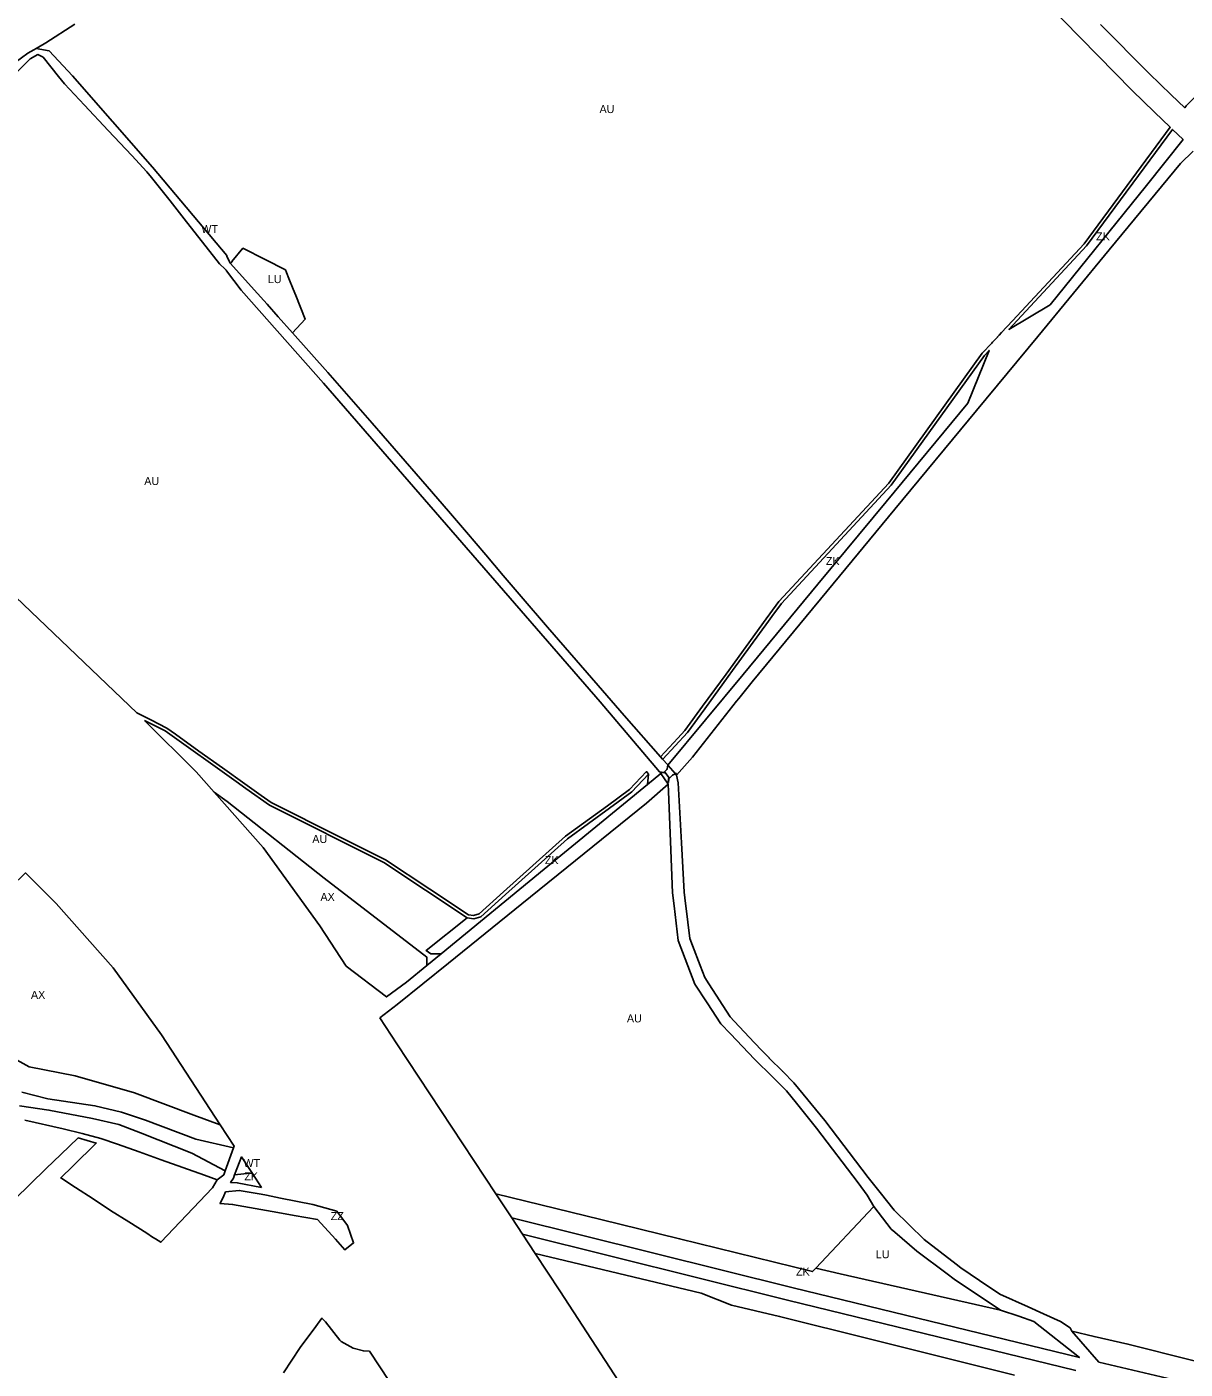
# Model space of a CAD drawing. Extents: x -545779 to -541342, y -1153413 to -1149956.
# Drawn here: x -543834 to -543110, y -1151300 to -1150461 of the extents above; entities that cross this region are included whole.
import ezdxf

# ---------------------------------------------------------------- set-up
doc = ezdxf.new("R2010")
doc.units = 0
for name, color, linetype in [('90640013', 7, 'Continuous'), ('90670013', 7, 'Continuous'), ('90710013', 7, 'Continuous'), ('90750013', 7, 'Continuous'), ('90760013', 7, 'Continuous'), ('90770013', 7, 'Continuous'), ('90910012', 7, 'Continuous')]:
    doc.layers.add(name, color=color, linetype=linetype)

msp = doc.modelspace()

# ---------------------------------------------------------------- linework, layer by layer
at = {"layer": '90640013'}
for points in [[(-543856.96, -1150495.34), (-543832.89, -1150477.96), (-543829.16, -1150475.78), (-543827.7, -1150474.93), (-543819.62, -1150476.53), (-543805.09, -1150492.17), (-543755.13, -1150549.13), (-543708.68, -1150604.37), (-543708.56, -1150604.72), (-543706.49, -1150609.12), (-543706.29, -1150609.34), (-543691.64, -1150625.75), (-543683.54, -1150634.82), (-543676.59, -1150642.6), (-543667.56, -1150652.71), (-543645.51, -1150677.5), (-543617.92, -1150709.21), (-543583.61, -1150748.73), (-543570.28, -1150764.08), (-543558.9, -1150777.31), (-543546.88, -1150791.44), (-543535.99, -1150804.25), (-543524.83, -1150817.37), (-543508.36, -1150836.61), (-543476.78, -1150872.96), (-543460.42, -1150891.69), (-543437.78, -1150917.57), (-543436.46, -1150919.09), (-543433.3, -1150922.7), (-543433.63, -1150925.18), (-543433.91, -1150925.46), (-543435.29, -1150926.98), (-543435.73, -1150927.36), (-543438.36, -1150927.01), (-543475.45, -1150883.26), (-543561.88, -1150783.67), (-543561.88, -1150783.67), (-543648.32, -1150684.08), (-543699.66, -1150626.08), (-543708.87, -1150613.91), (-543709.16, -1150613.52), (-543709.83, -1150612.64), (-543713.01, -1150609.72), (-543713.28, -1150609.47), (-543735.34, -1150581.48), (-543735.34, -1150581.48), (-543744.15, -1150570.29), (-543755.72, -1150555.62), (-543758.57, -1150552), (-543767.97, -1150541.96), (-543782.74, -1150526.2), (-543797.48, -1150510.48), (-543810.09, -1150497.01), (-543813.81, -1150492.41), (-543823.43, -1150480.51), (-543826.77, -1150478.79), (-543831.59, -1150481.42), (-543866.15, -1150515.56)], [(-543178.39, -1151301.1), (-543358.41, -1151257.17), (-543524.057, -1151215.846), (-543530.742, -1151205.708), (-543354.98, -1151249.39), (-543176.13, -1151292.96), (-543176.13, -1151292.96), (-543204.67, -1151270.37), (-543213.98, -1151267.2), (-543225.5, -1151263.28), (-543254.3, -1151243.94), (-543258.78, -1151240.57), (-543277.58, -1151226.45), (-543291.35, -1151214.66), (-543293.67, -1151212.67), (-543304.46, -1151198.58), (-543308.69, -1151191.46), (-543314.22, -1151183.8), (-543340.24, -1151149.63), (-543352.82, -1151134.09), (-543359.18, -1151126.23), (-543367.68, -1151117.79), (-543379.07, -1151106.47), (-543394.15, -1151090.66), (-543400.09, -1151084.43), (-543408.67, -1151071.25), (-543416.26, -1151059.6), (-543426.69, -1151032.45), (-543429.25, -1151010.65), (-543430.2, -1151002.57), (-543431.56, -1150970.58), (-543432.69, -1150939.38), (-543432.98, -1150934.6), (-543437.53, -1150927.99), (-543438.05, -1150927.38), (-543435.55, -1150927.71), (-543435.1, -1150927.22), (-543432.32, -1150930.66), (-543432.72, -1150931.07), (-543433.04, -1150933.57), (-543432.81, -1150933.61), (-543432.52, -1150931.31), (-543432.13, -1150930.89), (-543430.7, -1150929.43), (-543430.27, -1150928.97), (-543428.35, -1150928.34), (-543427.74, -1150929.04), (-543426.71, -1150933.89), (-543424.6, -1150971.44), (-543423.01, -1151002.24), (-543422.59, -1151005.62), (-543420.69, -1151021.01), (-543419.44, -1151031.07), (-543417.76, -1151035.48), (-543412.98, -1151048.07), (-543410.14, -1151055.53), (-543407.57, -1151059.54), (-543394.37, -1151080.15), (-543391.84, -1151082.82), (-543379.01, -1151096.37), (-543374.42, -1151101.21), (-543369.97, -1151105.7), (-543369.81, -1151105.87), (-543361.45, -1151114.32), (-543354.5, -1151121.33), (-543335.16, -1151144.92), (-543308.17, -1151180.51), (-543300.61, -1151189.88), (-543291.79, -1151200.81), (-543273, -1151219.27), (-543253.17, -1151234.66), (-543250.18, -1151236.98), (-543238.53, -1151244.79), (-543225.77, -1151253.35), (-543208.22, -1151261.31), (-543198.51, -1151265.71), (-543187.91, -1151270.51), (-543181.96, -1151274.48), (-543180.77, -1151276.4), (-543163.961, -1151295.825), (-542990.46, -1151336.67)], [(-543836.64, -1151127.19), (-543820.44, -1151131.33), (-543791.01, -1151135.61), (-543774.37, -1151139.55), (-543759.44, -1151144.59), (-543728.11, -1151156.46), (-543704.49, -1151161.98), (-543709.68, -1151176.38), (-543730.51, -1151165.23), (-543762.49, -1151152.65), (-543776.19, -1151147.43), (-543792.55, -1151143.69), (-543819.74, -1151138.33), (-543838.2, -1151135.78)]]:
    msp.add_lwpolyline(points, dxfattribs=at)
msp.add_lwpolyline([(-543703.84, -1151178.88), (-543699.584, -1151167.645), (-543692.716, -1151178.06), (-543694.1, -1151177.77)], close=True, dxfattribs=at)
at = {"layer": '90670013'}
msp.add_lwpolyline([(-543687.14, -1151190.91), (-543683.806, -1151191.571), (-543675.179, -1151193.284), (-543675.179, -1151193.284), (-543654.84, -1151197.32), (-543639.96, -1151201.49), (-543633.18, -1151210.51), (-543629.48, -1151221.37), (-543634.91, -1151225.67), (-543640.81, -1151219.02), (-543652.11, -1151206.75), (-543666.57, -1151204.23), (-543676.75, -1151202.34), (-543705.09, -1151197.25), (-543712.86, -1151196.79), (-543710.44, -1151192.02), (-543709.48, -1151189.44), (-543700.87, -1151188.52)], close=True, dxfattribs=at)
at = {"layer": '90710013'}
for points in [[(-543111.232, -1150531.92), (-543134.28, -1150560.52), (-543194.48, -1150635.21), (-543220.18, -1150650.51), (-543171.65, -1150598.32), (-543117.9, -1150525.589)], [(-543392.737, -1150863.69), (-543370.27, -1150832.8), (-543368.16, -1150829.86), (-543362.29, -1150821.83), (-543293.65, -1150747.91), (-543235.36, -1150666.74), (-543232.51, -1150663.7), (-543245.84, -1150696.55), (-543296.93, -1150758.24), (-543339.51, -1150809.68), (-543386.24, -1150866.12), (-543433.14, -1150922.75), (-543433.3, -1150922.7), (-543436.46, -1150919.09), (-543436.35, -1150918.98), (-543420.96, -1150902.48), (-543410.13, -1150887.6), (-543395.45, -1150867.42)], [(-543574.84, -1151040.74), (-543581.33, -1151040.8), (-543584.15, -1151038.63), (-543558.5, -1151018.16), (-543554.36, -1151018.79), (-543550.03, -1151017.5), (-543534.52, -1151003.56), (-543495.83, -1150968.78), (-543469.6, -1150949.67), (-543455.73, -1150939.56), (-543445.28, -1150928.5), (-543445.92, -1150934.89), (-543510.38, -1150987.81)], [(-543686.982, -1151186.756), (-543702.17, -1151183.73), (-543706.27, -1151183.57), (-543704.58, -1151180.83), (-543703.84, -1151178.88), (-543694.1, -1151177.77), (-543692.716, -1151178.06)], [(-543540.715, -1151190.584), (-543474.99, -1151206.7), (-543425.84, -1151218.75), (-543425.84, -1151218.75), (-543342.771, -1151239.283), (-543340.81, -1151237.2), (-543325.56, -1151240.65), (-543225.5, -1151263.28), (-543213.98, -1151267.2), (-543204.67, -1151270.37), (-543176.13, -1151292.96), (-543354.98, -1151249.39), (-543530.742, -1151205.708)]]:
    msp.add_lwpolyline(points, close=True, dxfattribs=at)
for points in [[(-543853.83, -1151099.45), (-543832.05, -1151111.38), (-543803.43, -1151116.87), (-543766.25, -1151127.49), (-543729.27, -1151141.61), (-543712.747, -1151147.495), (-543712.747, -1151147.495), (-543704.069, -1151160.82), (-543704.49, -1151161.98), (-543728.11, -1151156.46), (-543759.44, -1151144.59), (-543774.37, -1151139.55), (-543791.01, -1151135.61), (-543820.44, -1151131.33), (-543836.64, -1151127.19)], [(-543838.2, -1151135.78), (-543819.74, -1151138.33), (-543792.55, -1151143.69), (-543776.19, -1151147.43), (-543762.49, -1151152.65), (-543730.51, -1151165.23), (-543709.68, -1151176.38), (-543710.55, -1151178.78), (-543714.64, -1151182), (-543722.54, -1151178.99), (-543736.15, -1151174.3), (-543749.75, -1151169.5), (-543763.41, -1151164.4), (-543777, -1151159.58), (-543787.4, -1151156.11), (-543798.93, -1151152.89), (-543810.81, -1151150.09), (-543834.9, -1151144.58)], [(-543216.67, -1151303.95), (-543305.78, -1151281.7), (-543363.4, -1151267.31), (-543393.49, -1151260.23), (-543412.29, -1151252.82), (-543516.014, -1151228.043), (-543516.014, -1151228.043), (-543524.057, -1151215.846), (-543358.41, -1151257.17), (-543178.39, -1151301.1)], [(-542990.46, -1151336.67), (-543163.961, -1151295.825), (-543180.77, -1151276.4), (-543166.94, -1151279.89), (-543145.84, -1151284.58), (-543106.07, -1151294.56), (-543092.51, -1151297.96), (-543052.23, -1151308.78)]]:
    msp.add_lwpolyline(points, dxfattribs=at)
at = {"layer": '90750013'}
for points in [[(-543196.816, -1150446.451), (-543143.124, -1150501.272), (-543129.247, -1150514.814), (-543119.365, -1150524.197), (-543173.2, -1150597.05), (-543217.86, -1150645.08), (-543224.74, -1150652.49), (-543226.31, -1150654.16), (-543226.31, -1150654.16), (-543227.358, -1150655.277), (-543227.37, -1150655.29), (-543230.42, -1150658.54), (-543230.9, -1150659.05), (-543236.92, -1150665.47), (-543295.21, -1150746.65), (-543363.84, -1150820.56), (-543369.49, -1150828.33), (-543371.69, -1150831.35), (-543396.8, -1150865.87), (-543411.47, -1150886.04), (-543422.5, -1150901.2), (-543427.02, -1150906.04), (-543437.78, -1150917.57), (-543460.42, -1150891.69), (-543476.78, -1150872.96), (-543508.36, -1150836.61), (-543524.83, -1150817.37), (-543535.99, -1150804.25), (-543546.88, -1150791.44), (-543558.9, -1150777.31), (-543570.28, -1150764.08), (-543583.61, -1150748.73), (-543617.92, -1150709.21), (-543645.51, -1150677.5), (-543667.56, -1150652.71), (-543659.69, -1150644.11), (-543665.6, -1150629.43), (-543667.22, -1150625.41), (-543669.94, -1150618.67), (-543671.39, -1150615.05), (-543672.09, -1150613.32), (-543684.71, -1150606.9), (-543698.58, -1150599.85), (-543705.55, -1150608.02), (-543705.29, -1150608.29), (-543706.29, -1150609.34), (-543706.49, -1150609.12), (-543708.56, -1150604.72), (-543708.68, -1150604.37), (-543755.13, -1150549.13), (-543805.09, -1150492.17), (-543819.62, -1150476.53), (-543827.7, -1150474.93), (-543822.81, -1150472.07), (-543821.65, -1150471.39), (-543803.6, -1150459.91)], [(-543104.73, -1150447.88), (-543088.15, -1150466.06), (-543082.43, -1150472.34), (-543078.75, -1150476.37), (-543077.94, -1150478.69), (-543078.97, -1150479.78), (-543079.12, -1150479.93), (-543109.47, -1150510.9), (-543110.38, -1150512.08), (-543118.844, -1150504.007), (-543132.527, -1150490.655), (-543162.992, -1150460.034)], [(-543866.15, -1150515.56), (-543831.59, -1150481.42), (-543826.77, -1150478.79), (-543823.43, -1150480.51), (-543813.81, -1150492.41), (-543810.09, -1150497.01), (-543797.48, -1150510.48), (-543782.74, -1150526.2), (-543767.97, -1150541.96), (-543758.57, -1150552), (-543755.72, -1150555.62), (-543744.15, -1150570.29), (-543735.34, -1150581.48), (-543735.34, -1150581.48), (-543713.28, -1150609.47), (-543713.01, -1150609.72), (-543709.83, -1150612.64), (-543709.16, -1150613.52), (-543708.87, -1150613.91), (-543699.66, -1150626.08), (-543648.32, -1150684.08), (-543561.88, -1150783.67), (-543561.88, -1150783.67), (-543475.45, -1150883.26), (-543438.36, -1150927.01), (-543435.73, -1150927.36), (-543435.29, -1150926.98), (-543433.91, -1150925.46), (-543433.63, -1150925.18), (-543433.3, -1150922.7), (-543433.14, -1150922.75), (-543433.02, -1150922.78), (-543433.05, -1150922.99), (-543428.63, -1150928.03), (-543428.2, -1150927.89), (-543427.93, -1150928.2), (-543428.35, -1150928.34), (-543430.27, -1150928.97), (-543430.7, -1150929.43), (-543432.13, -1150930.89), (-543432.52, -1150931.31), (-543432.81, -1150933.61), (-543433.04, -1150933.57), (-543432.72, -1150931.07), (-543432.32, -1150930.66), (-543435.1, -1150927.22), (-543435.55, -1150927.71), (-543438.05, -1150927.38), (-543437.53, -1150927.99), (-543445.92, -1150934.89), (-543445.28, -1150928.5), (-543446.48, -1150926.86), (-543457.05, -1150938.05), (-543470.91, -1150948.15), (-543497.08, -1150967.22), (-543535.83, -1151002.06), (-543551.03, -1151015.72), (-543554.5, -1151016.74), (-543557.76, -1151016.25), (-543581.82, -1151000.28), (-543609.52, -1150981.9), (-543637.45, -1150967.92), (-543653.68, -1150959.8), (-543665.64, -1150953.82), (-543678.05, -1150947.61), (-543680.89, -1150946.19), (-543687.16, -1150941.72), (-543697.36, -1150934.46), (-543711.46, -1150924.42), (-543726.08, -1150914), (-543740.79, -1150903.51), (-543746.15, -1150899.7), (-543756.2, -1150894.58), (-543764.552, -1150890.325), (-543764.769, -1150890.108), (-543840.462, -1150817.893)], [(-543106.07, -1151294.56), (-543145.84, -1151284.58), (-543166.94, -1151279.89), (-543180.77, -1151276.4), (-543181.96, -1151274.48), (-543187.91, -1151270.51), (-543198.51, -1151265.71), (-543208.22, -1151261.31), (-543225.77, -1151253.35), (-543238.53, -1151244.79), (-543250.18, -1151236.98), (-543253.17, -1151234.66), (-543273, -1151219.27), (-543291.79, -1151200.81), (-543300.61, -1151189.88), (-543308.17, -1151180.51), (-543335.16, -1151144.92), (-543354.5, -1151121.33), (-543361.45, -1151114.32), (-543361.45, -1151114.32), (-543369.81, -1151105.87), (-543369.97, -1151105.7), (-543374.42, -1151101.21), (-543379.01, -1151096.37), (-543391.84, -1151082.82), (-543394.37, -1151080.15), (-543407.57, -1151059.54), (-543410.14, -1151055.53), (-543412.98, -1151048.07), (-543417.76, -1151035.48), (-543419.44, -1151031.07), (-543420.69, -1151021.01), (-543422.59, -1151005.62), (-543423.01, -1151002.24), (-543424.6, -1150971.44), (-543426.71, -1150933.89), (-543427.74, -1150929.04), (-543417.85, -1150917.85), (-543390.27, -1150882.92), (-543388.9, -1150881.22), (-543380.54, -1150870.84), (-543333.86, -1150814.34), (-543291.34, -1150762.87), (-543240.31, -1150701.11), (-543202.13, -1150654.9), (-543157.53, -1150600.92), (-543112.93, -1150546.93), (-543104.97, -1150539.21)], [(-543443.977, -1151338.286), (-543500.703, -1151251.262), (-543516.014, -1151228.043), (-543412.29, -1151252.82), (-543393.49, -1151260.23), (-543363.4, -1151267.31), (-543305.78, -1151281.7), (-543216.67, -1151303.95)]]:
    msp.add_lwpolyline(points, dxfattribs=at)
for points in [[(-543759.981, -1150894.897), (-543747.19, -1150901.41), (-543702.88, -1150932.98), (-543696.76, -1150937.34), (-543681.92, -1150947.91), (-543610.53, -1150983.63), (-543558.5, -1151018.16), (-543584.15, -1151038.63), (-543581.33, -1151040.8), (-543574.84, -1151040.74), (-543583.69, -1151048), (-543583.74, -1151042.73), (-543647.89, -1150993.43), (-543708.46, -1150945.44), (-543716.654, -1150939.687), (-543727.838, -1150927.049)], [(-543613.042, -1151080.7), (-543602.19, -1151072.41), (-543570.17, -1151046.52), (-543524.34, -1151009.46), (-543485.42, -1150977.98), (-543446.49, -1150946.51), (-543432.98, -1150934.6), (-543432.69, -1150939.38), (-543431.56, -1150970.58), (-543430.2, -1151002.57), (-543429.25, -1151010.65), (-543426.69, -1151032.45), (-543416.26, -1151059.6), (-543408.67, -1151071.25), (-543400.09, -1151084.43), (-543394.15, -1151090.66), (-543379.07, -1151106.47), (-543367.68, -1151117.79), (-543359.18, -1151126.23), (-543352.82, -1151134.09), (-543340.24, -1151149.63), (-543314.22, -1151183.8), (-543308.69, -1151191.46), (-543304.46, -1151198.58), (-543304.64, -1151198.78), (-543340.81, -1151237.2), (-543342.771, -1151239.283), (-543425.84, -1151218.75), (-543474.99, -1151206.7), (-543540.715, -1151190.584), (-543602.425, -1151097.003)]]:
    msp.add_lwpolyline(points, close=True, dxfattribs=at)
at = {"layer": '90760013'}
for points in [[(-543634.042, -1151048.453), (-543634.042, -1151048.453), (-543650.498, -1151023.182), (-543685.997, -1150974.326), (-543716.654, -1150939.687), (-543708.46, -1150945.44), (-543647.89, -1150993.43), (-543583.74, -1151042.73), (-543583.69, -1151048), (-543596.49, -1151058.45), (-543608.97, -1151067.59)], [(-543712.747, -1151147.495), (-543729.27, -1151141.61), (-543766.25, -1151127.49), (-543803.43, -1151116.87), (-543832.05, -1151111.38), (-543853.83, -1151099.45), (-543883.76, -1151079.27), (-543914.79, -1151053.54), (-543917.81, -1151050.47), (-543875.99, -1151010.48), (-543870.92, -1151015.46), (-543866.247, -1151022.12), (-543860.9, -1151015.8), (-543834.398, -1150990.189), (-543815.282, -1151009.31), (-543779.683, -1151049.534), (-543749.382, -1151091.238)]]:
    msp.add_lwpolyline(points, close=True, dxfattribs=at)
for points in [[(-543834.9, -1151144.58), (-543810.81, -1151150.09), (-543798.93, -1151152.89), (-543787.4, -1151156.11), (-543777, -1151159.58), (-543763.41, -1151164.4), (-543749.75, -1151169.5), (-543736.15, -1151174.3), (-543722.54, -1151178.99), (-543714.64, -1151182), (-543717.6, -1151186.99), (-543749.81, -1151220.95), (-543753.31, -1151218.74), (-543755, -1151217.67), (-543758.65, -1151215.35), (-543769.93, -1151208.25), (-543781.24, -1151201.11), (-543792.17, -1151193.81), (-543803.08, -1151186.76), (-543812.4, -1151180.74), (-543804.94, -1151173.42), (-543790.2, -1151158.97), (-543801.55, -1151155.71), (-543812.37, -1151166.19), (-543821.4, -1151174.93), (-543841.19, -1151194.27)], [(-543673.25, -1151302.44), (-543662.86, -1151286.76), (-543653.13, -1151273.5), (-543649.28, -1151268.29), (-543647.06, -1151270.71), (-543638.11, -1151282.16), (-543637.17, -1151283.03), (-543629.79, -1151287.1), (-543623.3, -1151288.83), (-543619.594, -1151288.947), (-543601.057, -1151317.058)]]:
    msp.add_lwpolyline(points, dxfattribs=at)
at = {"layer": '90770013'}
for points in [[(-543676.59, -1150642.6), (-543683.54, -1150634.82), (-543691.64, -1150625.75), (-543706.29, -1150609.34), (-543705.29, -1150608.29), (-543705.55, -1150608.02), (-543698.58, -1150599.85), (-543684.71, -1150606.9), (-543672.09, -1150613.32), (-543671.39, -1150615.05), (-543669.94, -1150618.67), (-543667.22, -1150625.41), (-543665.6, -1150629.43), (-543659.69, -1150644.11), (-543667.56, -1150652.71)], [(-543325.56, -1151240.65), (-543340.81, -1151237.2), (-543304.64, -1151198.78), (-543304.46, -1151198.58), (-543293.67, -1151212.67), (-543291.35, -1151214.66), (-543277.58, -1151226.45), (-543258.78, -1151240.57), (-543254.3, -1151243.94), (-543225.5, -1151263.28)]]:
    msp.add_lwpolyline(points, close=True, dxfattribs=at)
at = {"layer": '90910012'}
msp.add_lwpolyline([(-543583.69, -1151048), (-543583.74, -1151042.73), (-543647.89, -1150993.43), (-543708.46, -1150945.44), (-543716.654, -1150939.687)], dxfattribs=at)

# ---------------------------------------------------------------- texts
at = {"layer": '90640013'}
for p in [(-543724.59, -1150590.284), (-543698.278, -1151173.936)]:
    msp.add_text('WT', height=5, rotation=0, dxfattribs=at).set_placement(p)
at = {"layer": '90670013'}
msp.add_text('ZZ', height=5, rotation=360, dxfattribs=at).set_placement((-543643.77, -1151207.095))
at = {"layer": '90710013'}
msp.add_text('ZK', height=5, dxfattribs=at).set_placement((-543165.706, -1150594.894))
for p in [(-543334.485, -1150797.748), (-543510.008, -1150984.65), (-543697.704, -1151182.263), (-543353.116, -1151241.772)]:
    msp.add_text('ZK', height=5, rotation=360, dxfattribs=at).set_placement(p)
at = {"layer": '90750013'}
for rotation, p in [(360, (-543475.872, -1150515.36)), (0, (-543760.234, -1150747.765)), (360, (-543655.255, -1150971.449)), (360, (-543458.751, -1151083.551))]:
    msp.add_text('AU', height=5, rotation=rotation, dxfattribs=at).set_placement(p)
at = {"layer": '90760013'}
for p in [(-543650.172, -1151007.652), (-543830.995, -1151068.842)]:
    msp.add_text('AX', height=5, rotation=0, dxfattribs=at).set_placement(p)
at = {"layer": '90770013'}
for p in [(-543682.99, -1150621.605), (-543303.261, -1151230.93)]:
    msp.add_text('LU', height=5, rotation=0, dxfattribs=at).set_placement(p)

doc.saveas('drawing.dxf')
